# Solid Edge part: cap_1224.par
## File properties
Author: CADSoft
Template: Sync Iso Part.par
Last saved by: Sarvanan
Revision: 8
Application: Solid Edge
Accuracy: 0.990
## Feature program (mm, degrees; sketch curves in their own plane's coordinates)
sketch for "Hole_1" plane through (0, 0, 47.9577) normal (0, 0, 1) x-axis (0, 1, 0)
  hole centre (0, 0) bore radius 3
hole "Hole_1" diameter 6 through
pattern "unnamed Pattern 1" of "Hole_1"
sketch for "Hole_2" plane through (-40.0381, 8.231, 36) normal (0, 0, 1) x-axis (1, 0, 0)
  hole centre (1.0381, -8.231) bore radius 6
hole "Hole_2" diameter 12 through
sketch for "unnamed Hole 1" plane through (38.3695, 10.2267, 36) normal (0, 0, 1) x-axis (1, 0, 0)
  hole centre (0.6305, -10.2267) bore radius 6
hole "unnamed Hole 1" through
pattern "unnamed Pattern 2" of "Hole_2", "unnamed Hole 1"
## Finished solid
Body 1: solid body, 21 faces, 50 edges, 28 vertices.
  Faces by surface: plane 11, cylinder 10
  Edges by curve: line 30, circle 16, intersection 4
Bounding box of the edges (mm): 108.000 x 46.000 x 40.000, from (-54, -23, 8) to (54, 23, 48).
Cylindrical faces by radius (mm): R3 x1, R4 x1, R6 x2, R17 x2, R24.3516 x1, R48 x1, R54 x2
Planar faces by outward normal: +x 1, +y 1, +z 3, -x 1, -y 1, -z 4
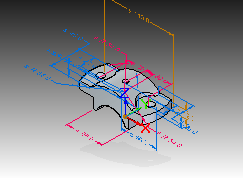
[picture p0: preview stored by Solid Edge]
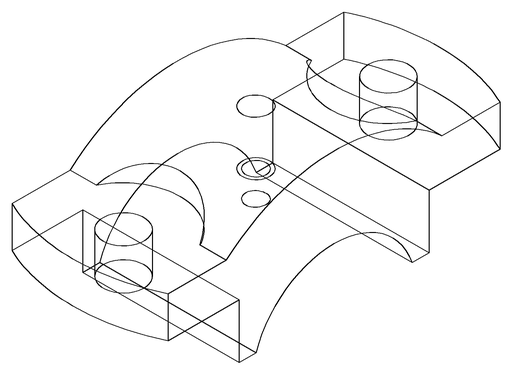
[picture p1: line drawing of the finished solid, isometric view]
